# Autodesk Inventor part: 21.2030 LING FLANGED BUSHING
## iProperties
Created: 2007-01
Part Number: 21.2030 LING FLANGED BUSHING
Document SubType Name: Modeling
Designer: Andy Moles
Material: Bronze, Soft Tin
Mass: 5.20631 g
Surface Area: 14.9383 cm^2
Volume: 0.586692 cm^3
Density: 8.874 g/cm^3
Author: Andy Moles
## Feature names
1. Extrusion1
2. Extrusion2
